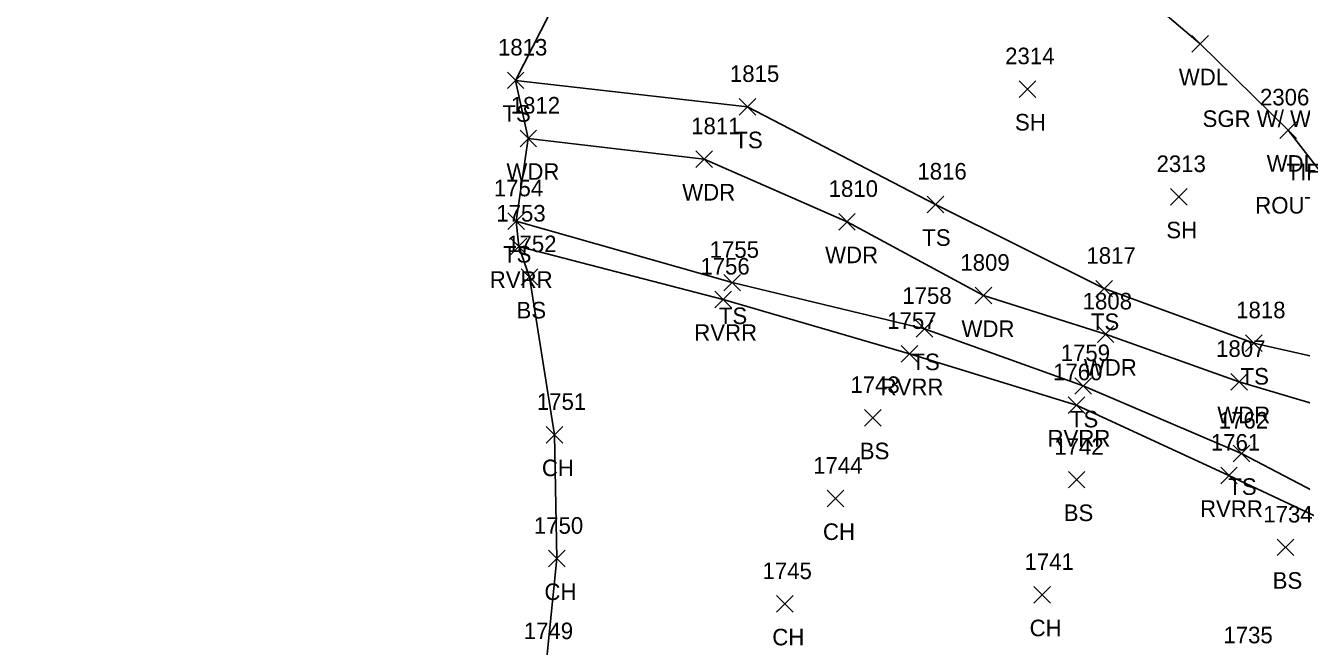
# Model space of a CAD drawing. Extents: x 1616726 to 1619875, y 273782 to 276557.
# Drawn here: x 1616729.6 to 1616883.5, y 276298.3 to 276373.3 of the extents above; entities that cross this region are included whole.
import ezdxf

# ---------------------------------------------------------------- set-up
doc = ezdxf.new("R2010")
doc.units = 0
for name, color, linetype in [('L_A', 7, 'Continuous'), ('L_I', 7, 'Continuous'), ('L_TIC', 7, 'Continuous'), ('LAWA', 7, 'Continuous'), ('LAWE', 7, 'Continuous'), ('LELB', 7, 'Continuous'), ('LSOGP', 7, 'Continuous'), ('R_C', 7, 'Continuous'), ('S_C', 7, 'Continuous')]:
    doc.layers.add(name, color=color, linetype=linetype)

msp = doc.modelspace()

# ---------------------------------------------------------------- linework, layer by layer
at = {"layer": 'L_TIC'}
for points in [[(1616870.25, 276370.07), (1616872.25, 276372.07)], [(1616872.25, 276370.07), (1616870.25, 276372.07)], [(1616787.7, 276365.66), (1616789.7, 276367.66)], [(1616789.7, 276365.66), (1616787.7, 276367.66)], [(1616849.42, 276364.61), (1616851.42, 276366.61)], [(1616851.42, 276364.61), (1616849.42, 276366.61)], [(1616815.67, 276362.47), (1616817.67, 276364.47)], [(1616817.67, 276362.47), (1616815.67, 276364.47)], [(1616880.86, 276359.64), (1616882.86, 276361.64)], [(1616882.86, 276359.64), (1616880.86, 276361.64)], [(1616789.23, 276358.66), (1616791.23, 276360.66)], [(1616791.23, 276358.66), (1616789.23, 276360.66)], [(1616810.43, 276356.16), (1616812.43, 276358.16)], [(1616812.43, 276356.16), (1616810.43, 276358.16)], [(1616867.68, 276351.6), (1616869.68, 276353.6)], [(1616869.68, 276351.6), (1616867.68, 276353.6)], [(1616838.33, 276350.69), (1616840.33, 276352.69)], [(1616840.33, 276350.69), (1616838.33, 276352.69)], [(1616787.77, 276348.67), (1616789.77, 276350.67)], [(1616789.77, 276348.67), (1616787.77, 276350.67)], [(1616827.66, 276348.6), (1616829.66, 276350.6)], [(1616829.66, 276348.6), (1616827.66, 276350.6)], [(1616788.07, 276345.62), (1616790.07, 276347.62)], [(1616790.07, 276345.62), (1616788.07, 276347.62)], [(1616789.37, 276341.93), (1616791.37, 276343.93)], [(1616791.37, 276341.93), (1616789.37, 276343.93)], [(1616813.8, 276341.25), (1616815.8, 276343.25)], [(1616815.8, 276341.25), (1616813.8, 276343.25)], [(1616858.66, 276340.53), (1616860.66, 276342.53)], [(1616860.66, 276340.53), (1616858.66, 276342.53)], [(1616812.73, 276339.23), (1616814.73, 276341.23)], [(1616814.73, 276339.23), (1616812.73, 276341.23)], [(1616844.11, 276339.69), (1616846.11, 276341.69)], [(1616846.11, 276339.69), (1616844.11, 276341.69)], [(1616837.02, 276335.69), (1616839.02, 276337.69)], [(1616839.02, 276335.69), (1616837.02, 276337.69)], [(1616858.85, 276335.02), (1616860.85, 276337.02)], [(1616860.85, 276335.02), (1616858.85, 276337.02)], [(1616835.2, 276332.67), (1616837.2, 276334.67)], [(1616837.2, 276332.67), (1616835.2, 276334.67)], [(1616876.71, 276333.95), (1616878.71, 276335.95)], [(1616878.71, 276333.95), (1616876.71, 276335.95)], [(1616856.13, 276328.78), (1616858.13, 276330.78)], [(1616858.13, 276328.78), (1616856.13, 276330.78)], [(1616874.94, 276329.29), (1616876.94, 276331.29)], [(1616876.94, 276329.29), (1616874.94, 276331.29)], [(1616855.33, 276326.47), (1616857.33, 276328.47)], [(1616857.33, 276326.47), (1616855.33, 276328.47)], [(1616830.76, 276324.94), (1616832.76, 276326.94)], [(1616832.76, 276324.94), (1616830.76, 276326.94)], [(1616792.39, 276322.9), (1616794.39, 276324.9)], [(1616794.39, 276322.9), (1616792.39, 276324.9)], [(1616875.23, 276320.64), (1616877.23, 276322.64)], [(1616877.23, 276320.64), (1616875.23, 276322.64)], [(1616855.35, 276317.48), (1616857.35, 276319.48)], [(1616857.35, 276317.48), (1616855.35, 276319.48)], [(1616873.72, 276317.98), (1616875.72, 276319.98)], [(1616875.72, 276317.98), (1616873.72, 276319.98)], [(1616826.28, 276315.2), (1616828.28, 276317.2)], [(1616828.28, 276315.2), (1616826.28, 276317.2)], [(1616880.55, 276309.31), (1616882.55, 276311.31)], [(1616882.55, 276309.31), (1616880.55, 276311.31)], [(1616792.68, 276307.95), (1616794.68, 276309.95)], [(1616794.68, 276307.95), (1616792.68, 276309.95)], [(1616851.19, 276303.58), (1616853.19, 276305.58)], [(1616853.19, 276303.58), (1616851.19, 276305.58)], [(1616820.16, 276302.48), (1616822.16, 276304.48)], [(1616822.16, 276302.48), (1616820.16, 276304.48)]]:
    msp.add_lwpolyline(points, dxfattribs=at)
at = {"layer": 'LAWA'}
for points in [[(1616926.41, 276312.56), (1616914.58, 276324.87), (1616905.26, 276338.6), (1616897.95, 276344.34), (1616892.13, 276347.37), (1616881.86, 276360.64), (1616871.25, 276371.07), (1616853.28, 276386.36), (1616841.14, 276384.08), (1616808.16, 276401.96), (1616800.62, 276406.17), (1616775.17, 276427.7), (1616751.6, 276451.28), (1616729.6, 276454.6)], [(1616922.59, 276307.33), (1616910.16, 276317.69), (1616893.44, 276325.1), (1616875.94, 276330.29), (1616859.85, 276336.02), (1616845.11, 276340.69), (1616828.66, 276349.6), (1616811.43, 276357.16), (1616790.23, 276359.66)]]:
    msp.add_lwpolyline(points, dxfattribs=at)
at = {"layer": 'LAWE'}
msp.add_lwpolyline([(1616789.07, 276346.62), (1616813.73, 276340.23), (1616836.2, 276333.67), (1616856.33, 276327.47), (1616874.72, 276318.98), (1616895.4, 276309.26), (1616910.77, 276301.56), (1616920.92, 276300.83), (1616931.35, 276302.77), (1616941.57, 276299.74), (1616947.81, 276295.8), (1616953.39, 276297.47), (1616960.89, 276300.06), (1616975.49, 276304.63), (1616989.93, 276306.41), (1617005.69, 276306.57), (1617020.09, 276309.06), (1617036.57, 276315.22), (1617052.5, 276318.39), (1617064.66, 276321.24), (1617083.34, 276325.98), (1617106.13, 276330.76), (1617129.7, 276333.81)], dxfattribs=at)
at = {"layer": 'LELB'}
for points in [[(1616788.7, 276366.66), (1616816.67, 276363.47), (1616839.33, 276351.69), (1616859.66, 276341.53), (1616877.71, 276334.95), (1616896.26, 276330.77), (1616910.34, 276321.96)], [(1616788.77, 276349.67), (1616814.8, 276342.25), (1616838.02, 276336.69), (1616857.13, 276329.78), (1616876.23, 276321.64), (1616896.05, 276311.27), (1616911.4, 276303.39), (1616919.94, 276303.32)]]:
    msp.add_lwpolyline(points, dxfattribs=at)
at = {"layer": 'LSOGP'}
msp.add_lwpolyline([(1616794.81, 276378.69), (1616788.7, 276366.66), (1616790.23, 276359.66), (1616788.77, 276349.67), (1616789.07, 276346.62), (1616790.37, 276342.93), (1616793.39, 276323.9), (1616793.68, 276308.95), (1616792.38, 276296.23)], dxfattribs=at)

# ---------------------------------------------------------------- texts
at = {"layer": 'L_A'}
for s, p in [('WDL', (1616868.67, 276366.07)), ('TS', (1616787.11, 276361.66)), ('SH', (1616848.91, 276360.61)), ('TS', (1616815.08, 276358.47)), ('WDR', (1616787.59, 276354.66)), ('WDL', (1616879.27, 276355.64)), ('WDR', (1616808.79, 276352.16)), ('TS', (1616837.74, 276346.69)), ('SH', (1616867.17, 276347.6)), ('TS', (1616787.18, 276344.67)), ('WDR', (1616826.02, 276344.6)), ('RVRR', (1616785.58, 276341.62)), ('BS', (1616788.81, 276337.93)), ('TS', (1616813.21, 276337.25)), ('WDR', (1616842.47, 276335.69)), ('TS', (1616858.07, 276336.53)), ('RVRR', (1616810.24, 276335.23)), ('TS', (1616836.43, 276331.69)), ('WDR', (1616857.22, 276331.02)), ('TS', (1616876.12, 276329.95)), ('RVRR', (1616832.71, 276328.67)), ('WDR', (1616873.31, 276325.29)), ('TS', (1616855.54, 276324.78)), ('RVRR', (1616852.84, 276322.47)), ('BS', (1616830.2, 276320.94)), ('CH', (1616791.87, 276318.9)), ('TS', (1616874.64, 276316.64)), ('BS', (1616854.79, 276313.48)), ('RVRR', (1616871.23, 276313.98)), ('CH', (1616825.76, 276311.2)), ('BS', (1616879.99, 276305.31)), ('CH', (1616792.17, 276303.95)), ('CH', (1616850.68, 276299.58)), ('CH', (1616819.65, 276298.48))]:
    msp.add_text(s, height=2, dxfattribs=at).set_placement(p)
at = {"layer": 'L_I'}
for s, p in [('1813', (1616786.57, 276369.66)), ('2314', (1616847.73, 276368.61)), ('1815', (1616814.54, 276366.47)), ('2306', (1616878.46, 276363.64)), ('1812', (1616788.11, 276362.66)), ('1811', (1616809.87, 276360.16)), ('1816', (1616837.15, 276354.69)), ('2313', (1616865.99, 276355.6)), ('1754', (1616786.07, 276352.67)), ('1810', (1616826.45, 276352.6)), ('1753', (1616786.37, 276349.62)), ('1752', (1616787.68, 276345.93)), ('1755', (1616812.1, 276345.25)), ('1809', (1616842.33, 276343.69)), ('1817', (1616857.53, 276344.53)), ('1756', (1616810.98, 276343.23)), ('1758', (1616835.33, 276339.69)), ('1808', (1616857.08, 276339.02)), ('1818', (1616875.59, 276337.95)), ('1757', (1616833.51, 276336.67)), ('1759', (1616854.43, 276332.78)), ('1807', (1616873.17, 276333.29)), ('1760', (1616853.51, 276330.47)), ('1743', (1616829.07, 276328.94)), ('1751', (1616791.26, 276326.9)), ('1762', (1616873.49, 276324.64)), ('1761', (1616872.54, 276321.98)), ('1742', (1616853.66, 276321.48)), ('1744', (1616824.58, 276319.2)), ('1734', (1616878.86, 276313.31)), ('1750', (1616790.9, 276311.95)), ('1745', (1616818.47, 276306.48)), ('1741', (1616850.07, 276307.58)), ('1749', (1616789.68, 276299.23)), ('1735', (1616874.05, 276298.73))]:
    msp.add_text(s, height=2, dxfattribs=at).set_placement(p)
at = {"layer": 'R_C'}
for s, p in [('SGR W/ WOOD POSTS', (1616871.54, 276361.04)), ('TIE=5.966', (1616881.67, 276354.59))]:
    msp.add_text(s, height=2, dxfattribs=at).set_placement(p)
at = {"layer": 'S_C'}
msp.add_text('ROUTE   DIRECTION', height=2, dxfattribs=at).set_placement((1616877.89, 276350.59))

doc.saveas('drawing.dxf')
